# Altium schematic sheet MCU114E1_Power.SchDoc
size 431 x 279 mm; Date: Not shown in title block; ApprovedBy: Not shown in title block; CheckedBy: Not shown in title block; Author: Not shown in title block; CompanyName: Not shown in title block; Engineer: Not shown in title block; Organization: Not shown in title block; Address1: Not shown in title block; Address2: Not shown in title block; Address3: Not shown in title block; Address4: Not shown in title block; DocumentNumber: 5; Revision: Use project parameter SCH_Rev; SheetNumber: 5; SheetTotal: 11; PageSetup: Record=PageOptions¦CenterHorizontal=True¦CenterVertical=True¦PrintScale=1.00¦XCorrection=1.00¦YCorrection=1.00¦PrintKind=0¦BorderSize=5000000¦LeftOffset=0¦BottomOffset=0¦Orientation=2¦PaperLength=1000¦PaperWidth=1000¦Scale=100¦PaperSource=15¦PrintQuality=600¦MediaType=1¦DitherType=10¦PaperKind=Letter¦PrintScaleMode=1
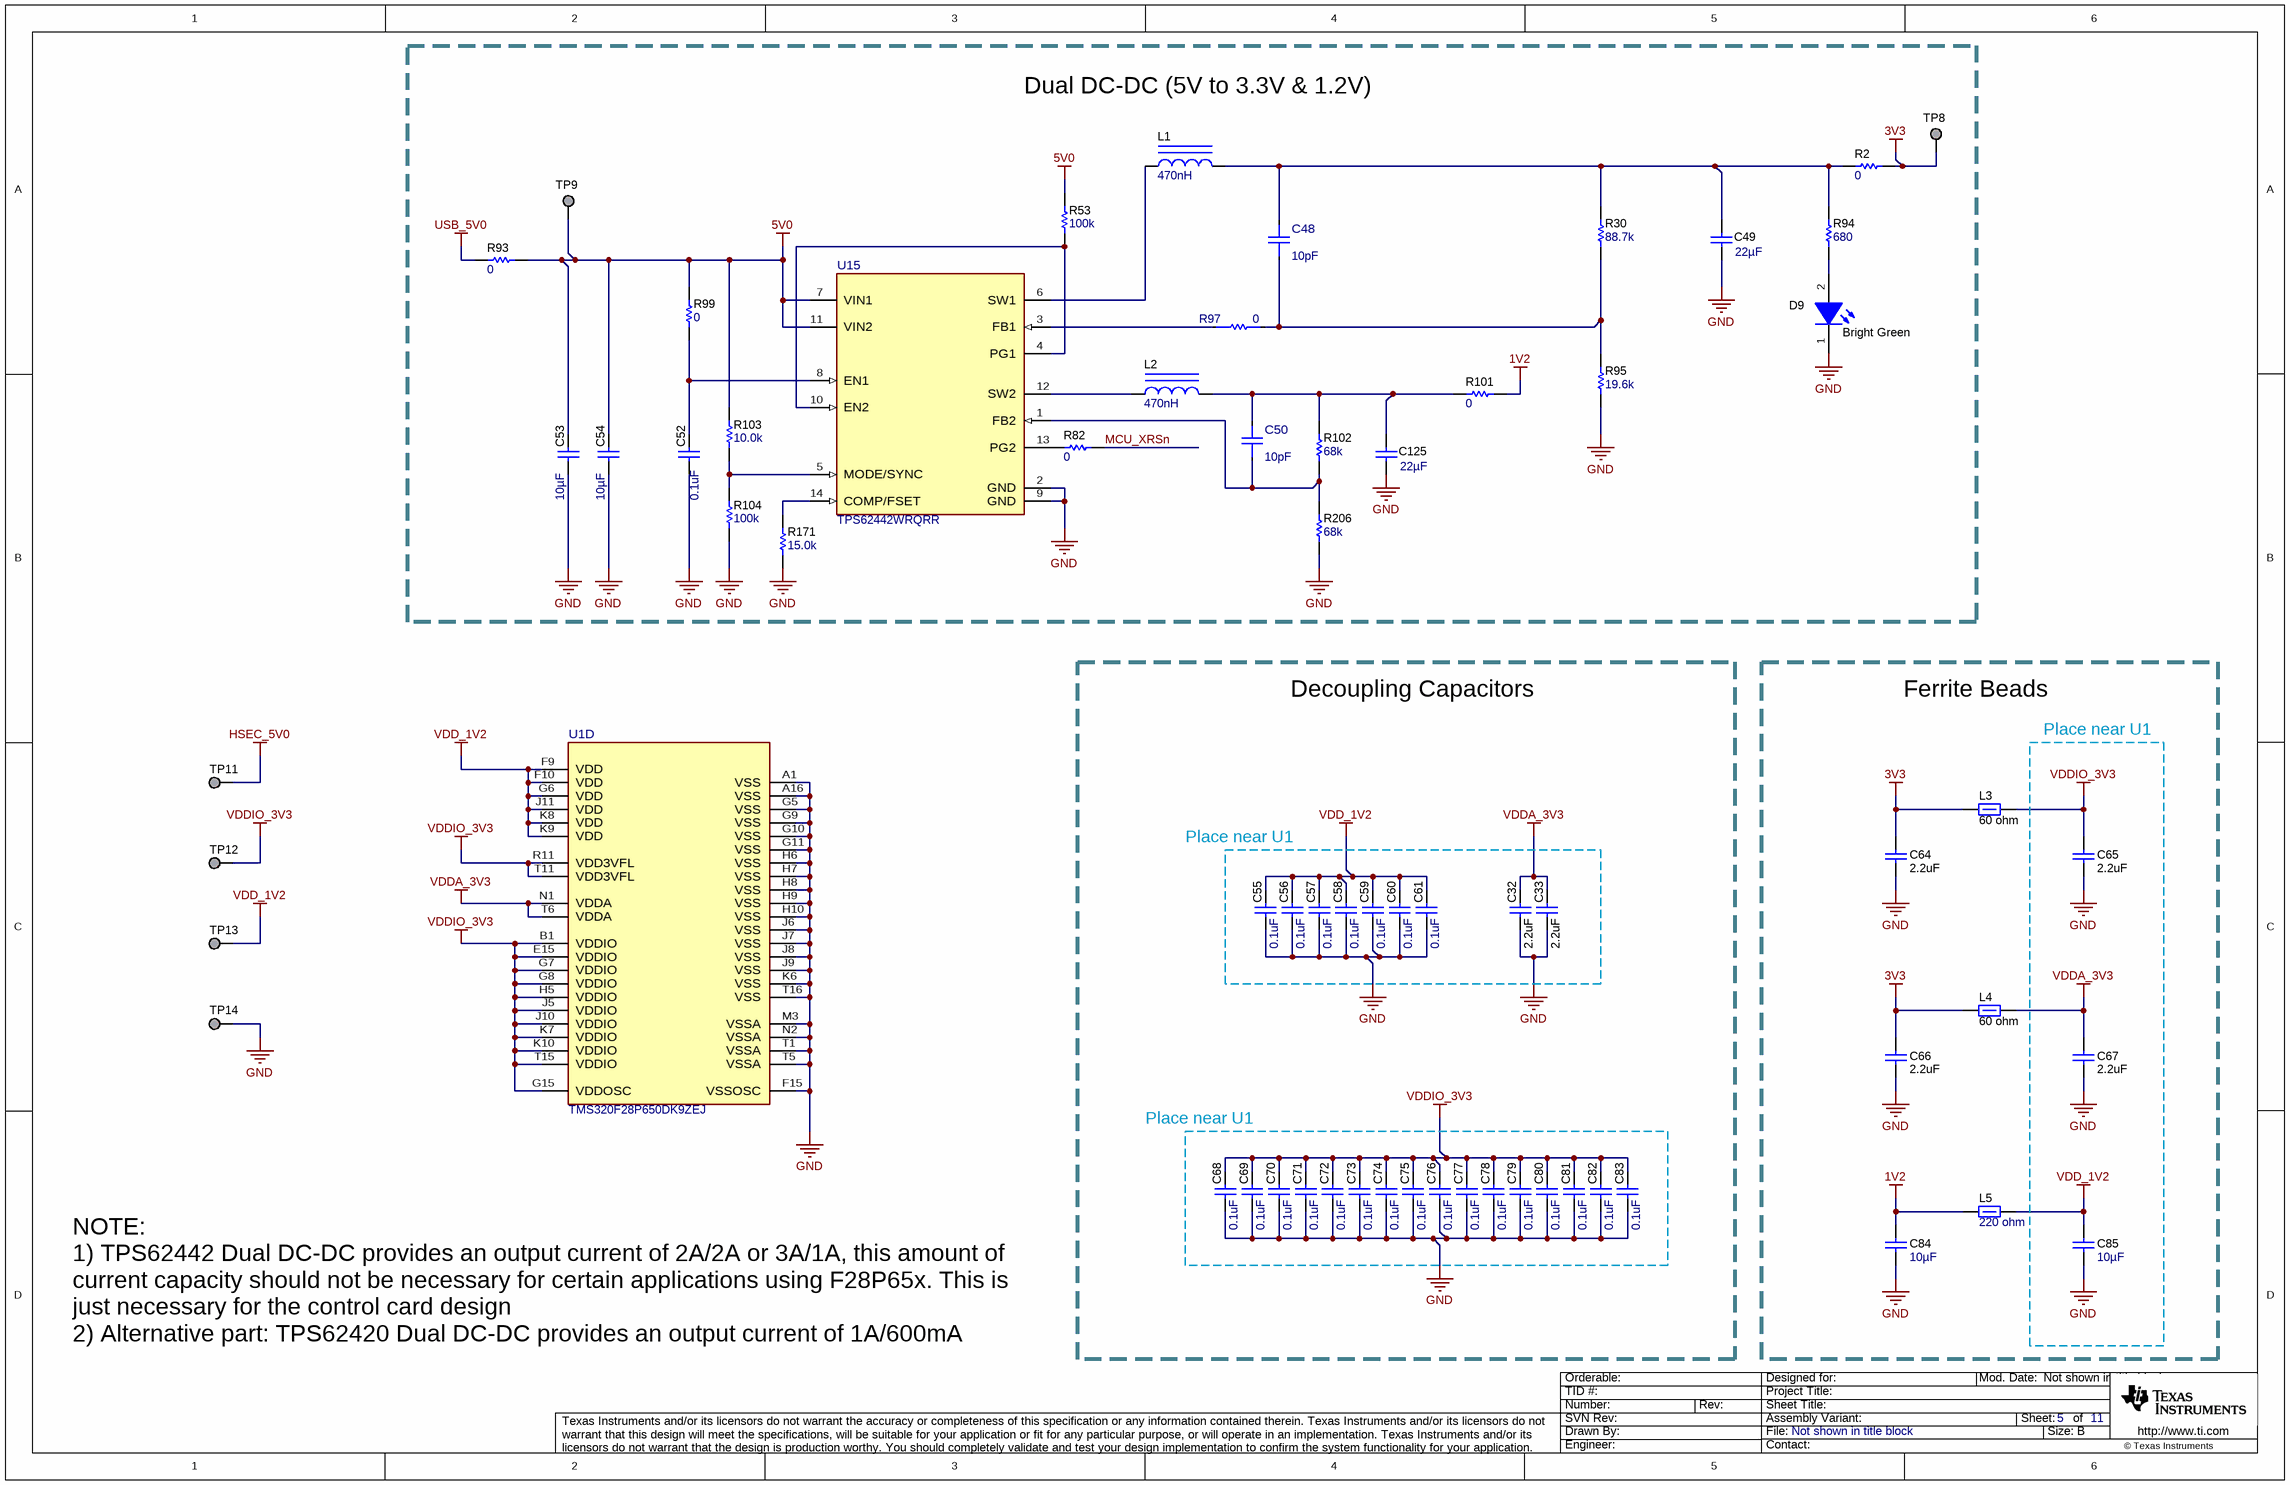
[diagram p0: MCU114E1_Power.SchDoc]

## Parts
C32  ValueDisplayed: 2.2uF  [0603]  (hidden comment: 885012106018)
C33  ValueDisplayed: 2.2uF  [0603]  (hidden comment: 885012106018)
C48  ValueDisplayed: 10pF  [FP-06033A100JAT2A_0603-MFG]  (hidden comment: 06033A100JAT2A)
C49  ValueDisplayed: 22µF  [0805_150]  (hidden comment: 885012107011)
C50  ValueDisplayed: 10pF  [FP-06033A100JAT2A_0603-MFG]  (hidden comment: 06033A100JAT2A)
C52  ValueDisplayed: 0.1uF  [0402]  (hidden comment: 885012205037)
C53  ValueDisplayed: 10µF  [0603]  (hidden comment: GRM188R61C106KAALD)
C54  ValueDisplayed: 10µF  [0603]  (hidden comment: GRM188R61C106KAALD)
C55  ValueDisplayed: 0.1uF  [0402]  (hidden comment: 885012205037)
C56  ValueDisplayed: 0.1uF  [0402]  (hidden comment: 885012205037)
C57  ValueDisplayed: 0.1uF  [0402]  (hidden comment: 885012205037)
C58  ValueDisplayed: 0.1uF  [0402]  (hidden comment: 885012205037)
C59  ValueDisplayed: 0.1uF  [0402]  (hidden comment: 885012205037)
C60  ValueDisplayed: 0.1uF  [0402]  (hidden comment: 885012205037)
C61  ValueDisplayed: 0.1uF  [0402]  (hidden comment: 885012205037)
C64  ValueDisplayed: 2.2uF  [0603]  (hidden comment: 885012106018)
C65  ValueDisplayed: 2.2uF  [0603]  (hidden comment: 885012106018)
C66  ValueDisplayed: 2.2uF  [0603]  (hidden comment: 885012106018)
C67  ValueDisplayed: 2.2uF  [0603]  (hidden comment: 885012106018)
C68  ValueDisplayed: 0.1uF  [0402]  (hidden comment: 885012205037)
C69  ValueDisplayed: 0.1uF  [0402]  (hidden comment: 885012205037)
C70  ValueDisplayed: 0.1uF  [0402]  (hidden comment: 885012205037)
C71  ValueDisplayed: 0.1uF  [0402]  (hidden comment: 885012205037)
C72  ValueDisplayed: 0.1uF  [0402]  (hidden comment: 885012205037)
C73  ValueDisplayed: 0.1uF  [0402]  (hidden comment: 885012205037)
C74  ValueDisplayed: 0.1uF  [0402]  (hidden comment: 885012205037)
C75  ValueDisplayed: 0.1uF  [0402]  (hidden comment: 885012205037)
C76  ValueDisplayed: 0.1uF  [0402]  (hidden comment: 885012205037)
C77  ValueDisplayed: 0.1uF  [0402]  (hidden comment: 885012205037)
C78  ValueDisplayed: 0.1uF  [0402]  (hidden comment: 885012205037)
C79  ValueDisplayed: 0.1uF  [0402]  (hidden comment: 885012205037)
C80  ValueDisplayed: 0.1uF  [0402]  (hidden comment: 885012205037)
C81  ValueDisplayed: 0.1uF  [0402]  (hidden comment: 885012205037)
C82  ValueDisplayed: 0.1uF  [0402]  (hidden comment: 885012205037)
C83  ValueDisplayed: 0.1uF  [0402]  (hidden comment: 885012205037)
C84  ValueDisplayed: 10µF  [0603]  (hidden comment: GRM188R61C106KAALD)
C85  ValueDisplayed: 10µF  [0603]  (hidden comment: GRM188R61C106KAALD)
C125  ValueDisplayed: 22µF  [0805_150]  (hidden comment: 885012107011)
D9  value Bright Green  [WL-SMCW_Green_0805]  (hidden comment: 150080VS75000)
L1  ValueDisplayed: 470nH  [XFL4015]  (hidden comment: XFL4015-471MEC)
L2  ValueDisplayed: 470nH  [XFL4015]  (hidden comment: XFL4015-471MEC)
L3  60 ohm  [0805_HV]
L4  60 ohm  [0805_HV]
L5  value 220 ohm  [0805_HV]  (hidden comment: BLM21PG221SN1D)
R2  ValueDisplayed: 0  [0402]  (hidden comment: CRCW04020000Z0EDHP)
R30  ValueDisplayed: 88.7k  [0402]  (hidden comment: CRCW040288K7FKED)
R53  ValueDisplayed: 100k  [0603]  (hidden comment: CRCW0603100KJNEA)
R82  ValueDisplayed: 0  [0402]  (hidden comment: CRCW04020000Z0EDHP)
R93  ValueDisplayed: 0  [0402]  (hidden comment: CRCW04020000Z0EDHP)
R94  ValueDisplayed: 680  [0402]  (hidden comment: CRCW0402680RJNED)
R95  ValueDisplayed: 19.6k  [0402]  (hidden comment: CRCW040219K6FKED)
R97  0  [FP-CRCW04020000Z0EDC_0402-MFG]
R99  ValueDisplayed: 0  [0402]  (hidden comment: CRCW04020000Z0EDHP)
R101  ValueDisplayed: 0  [0402]  (hidden comment: CRCW04020000Z0EDHP)
R102  ValueDisplayed: 68k  [0402]  (hidden comment: CRCW040268K0JNED)
R103  ValueDisplayed: 10.0k  [0402]  (hidden comment: AC0402FR-0710KL)
R104  ValueDisplayed: 100k  [0603]  (hidden comment: CRCW0603100KJNEA)
R171  ValueDisplayed: 15.0k  [0402]  (hidden comment: CRCW040215K0FKED)
R206  ValueDisplayed: 68k  [0402]  (hidden comment: CRCW040268K0JNED)
TP8  TESTPOINT  [TP_50MIL-25MILHOLE]  (value not drawn)  (no BOM)
TP9  TESTPOINT  [TP_50MIL-25MILHOLE]  (value not drawn)  (no BOM)
TP11  TESTPOINT  [TP_50MIL-25MILHOLE]  (value not drawn)  (no BOM)
TP12  TESTPOINT  [TP_50MIL-25MILHOLE]  (value not drawn)  (no BOM)
TP13  TESTPOINT  [TP_50MIL-25MILHOLE]  (value not drawn)  (no BOM)
TP14  TESTPOINT  [TP_50MIL-25MILHOLE]  (value not drawn)  (no BOM)
U1  TMS320F28P650DK9ZEJ  [ZEJ0256A-MFG]  (part D of 4)
U15  TPS62442WRQRR  [RQR0014A-MFG]

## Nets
1V2: C84.1 L5.1 R101.2
3V3: C64.1 C66.1 L3.1 L4.1 R2.2 TP8.1
5V0: C53.1 C54.1 R53.2 R93.1 R99.2 R103.2 TP9.1 U15.7(VIN1) U15.11(VIN2)
GND: C32.2 C33.2 C49.2 C52.2 C53.2 C54.2 C55.2 C56.2 C57.2 C58.2 C59.2 C60.2 C61.2 C64.2 C65.2 C66.2 C67.2 C68.2 C69.2 C70.2 C71.2 C72.2 C73.2 C74.2 C75.2 C76.2 C77.2 C78.2 C79.2 C80.2 C81.2 C82.2 C83.2 C84.2 C85.2 C125.2 D9.1(K) R95.1 R104.1 R171.1 R206.1 TP14.1 U1.A1(VSS) U1.A16(VSS) U1.F15(VSSOSC) U1.G5(VSS) U1.G9(VSS) U1.G10(VSS) U1.G11(VSS) U1.H6(VSS) U1.H7(VSS) U1.H8(VSS) U1.H9(VSS) U1.H10(VSS) U1.J6(VSS) U1.J7(VSS) U1.J8(VSS) U1.J9(VSS) U1.K6(VSS) U1.M3(VSSA) U1.N2(VSSA) U1.T1(VSSA) U1.T5(VSSA) U1.T16(VSS) U15.2(GND) U15.9(GND)
HSEC_5V0: TP11.1
USB_5V0: R93.2
VDD_1V2: C55.1 C56.1 C57.1 C58.1 C59.1 C60.1 C61.1 C85.1 L5.2 TP13.1 U1.F9(VDD) U1.F10(VDD) U1.G6(VDD) U1.J11(VDD) U1.K8(VDD) U1.K9(VDD)
VDDA_3V3: C32.1 C33.1 C67.1 L4.2 U1.N1(VDDA) U1.T6(VDDA)
VDDIO_3V3: C65.1 C68.1 C69.1 C70.1 C71.1 C72.1 C73.1 C74.1 C75.1 C76.1 C77.1 C78.1 C79.1 C80.1 C81.1 C82.1 C83.1 L3.2 TP12.1 U1.B1(VDDIO) U1.E15(VDDIO) U1.G7(VDDIO) U1.G8(VDDIO) U1.G15(VDDOSC) U1.H5(VDDIO) U1.J5(VDDIO) U1.J10(VDDIO) U1.K7(VDDIO) U1.K10(VDDIO) U1.R11(VDD3VFL) U1.T11(VDD3VFL) U1.T15(VDDIO)
MCU_XRSn: R82.1
NetC48_1: C48.1 R30.1 R95.2 R97.2
NetC48_2: C48.2 C49.1 L1.2 R2.1 R30.2 R94.2
NetC50_1: C50.1 R102.1 R206.2 U15.1(FB2)
NetC50_2: C50.2 C125.1 L2.2 R101.1 R102.2
NetC52_1: C52.1 R99.1 U15.8(EN1)
NetD9_2: D9.2(A) R94.1
NetL1_1: L1.1 U15.6(SW1)
NetL2_1: L2.1 U15.12(SW2)
NetR53_1: R53.1 U15.4(PG1) U15.10(EN2)
NetR82_2: R82.2 U15.13(PG2)
NetR97_1: R97.1 U15.3(FB1)
NetR103_1: R103.1 R104.2 U15.5(MODE/SYNC)
NetR171_2: R171.2 U15.14(COMP/FSET)

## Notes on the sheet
- Dual DC-DC (5V to 3.3V & 1.2V)
- Decoupling Capacitors
- Ferrite Beads
- Place near U1
- NOTE:
  1) TPS62442 Dual DC-DC provides an output current of 2A/2A or 3A/1A, this amount of current capacity should not be necessary for certain applications using F28P65x. This is just necessary for the control card design
  2) Alternative part: TPS62420 Dual DC-DC provides an output current of 1A/600mA

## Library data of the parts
C32 C33 C64-C67 = CMP-0006825-5: CAP, CERM, 2.2 uF, 16 V, +/- 20%, X5R, 0603; Manufacturer: Wurth Elektronik; TaMin_C: -55°C; Polarized: N; SizeAreaWB_mm2: 4.68; Value1: Unknown; U/M: EA; Value: 2.2uF; TaMax_C: 85°C; SizeZ_mm: 1; SizeX_mm: 1.6; SizeY_mm: 0.8; Value2: 16V; SizeArea_mm2: 1.28; Cap_F: 2.2µF; AEC Category: Q200
C48 C50 = CMP-0090724-1: 10pF ±5% 25V Ceramic Capacitor C0G, NP0 0603 (1608 Metric); Manufacturer: AVX; TempCo: 30ppm/°C; AEC Qualified: No; SizeZ_mm: 0.9mm
C49 C125 = CMP-0078153-1: CAP, CERM, 22 µF, 10 V,+/- 20%, X5R, 0805; Manufacturer: Wurth Elektronik; TaMin_C: -55°C; Polarized: N; SizeAreaWB_mm2: 6.75; U/M: EA; Value: 22uF; TaMax_C: 85°C; SizeZ_mm: 1.5; SizeX_mm: 2; SizeY_mm: 1.25; Cap_Case: 0805; Value2: 10V; SizeArea_mm2: 2.5; AEC Category: Q200
C52 C55-C61 C68-C83 = CMP-0006228-2: CAP, CERM, 0.1 uF, 16 V, +/- 10%, X7R, 0402; Manufacturer: Wurth Elektronik; TaMin_C: -55°C; Polarized: N; SizeAreaWB_mm2: 3; Value1: Unknown; U/M: EA; Value: 0.1uF; TaMax_C: 125°C; SizeZ_mm: 0.6; SizeX_mm: 1; SizeY_mm: 0.5; Value2: 16V; Cap_F: 100nF; AEC Category: Q200
C53 C54 C84 C85 = CMP-0086225-1: CAP, CERM, 10 µF, 16 V,+/- 10%, X5R, 0603; Manufacturer: MuRata; SizeZ_mm: 1; SizeX_mm: 1.6; SizeArea_mm2: 1.28; VDC_V: 16V; U/M: EA; AEC Category: Q200; SizeY_mm: 0.8; Polarized: N; TaMax_C: 85°C; Value: 10uF; SizeAreaWB_mm2: 4.68; TaMin_C: -55°C
D9 = CMP-0002960-2: LED, Bright Green, SMD; Manufacturer: Wurth Elektronik; Type: AlInGaP; Vf_V: 2V; Io_A: 20mA; Vr_V: 5V; Tjmax_C: 85°C; Power_TotalModule: 72mW; Value1: 0.072W; Angle: 140; U/M: EA
L1 L2 = CMP-0061147-1: Inductor, Shielded, Composite, 470 nH, 3.5 A, 0.0076 ohm, SMD; Manufacturer: Coilcraft; Isat: 3.5A @ 10% inductance drop; Irms: 9.1A @ 20C rise; Green_Lifecycle: Not Set; SizeAreaWB_mm2: 28.09; DCR_ohm: 7.6m; Green_REACh: Incomplete; Value: 470nH; Imax_A: 3.5A; SizeZ_mm: 1.6; SizeX_mm: 4.3; SizeArea_mm2: 18.49; AEC Category: Q200
L3 L4 = CMP-0003093-1: Ferrite Bead, 60 ohm @ 100 MHz, 3 A, 0805; Manufacturer: Wurth Elektronik; PartNumber: 742792063; Ztyp@1GHz_Ohm: 95.384; ZTyp@100MHz_Ohm: 60; SizeAreaWB_mm2: 6.75; DCR_ohm: 0.025; Value1: 0.025 ohm; Imax_A: 3A; SizeZ_mm: 1.45; SizeX_mm: 2; SizeY_mm: 1.25; SizeArea_mm2: 2.5
L5 = CMP-0003363-1: Ferrite Bead, 220 ohm @ 100 MHz, 2 A, 0805; Manufacturer: MuRata; Imax_A: 2A; DCR_ohm: 45m; Value1: 0.045 ohm; ZTyp@100MHz_Ohm: 220; SizeArea_mm2: 2.5; SizeAreaWB_mm2: 6.75; SizeX_mm: 2; SizeY_mm: 1.25; SizeZ_mm: 1.45
R2 R82 R93 R99 R101 = CMP-0081856-1: RES, 0, 0%, 0.2 W, AEC-Q200 Grade 0, 0402; Manufacturer: Vishay-Dale; SizeAreaWB_mm2: 3; SizeArea_mm2: 0.5; AEC Qualified: Y; AEC Category: Q200; Value: 0; SizeZ_mm: 0.6; Power_W: 200mW; VDC_V: 50V; Value2: 0.2W; SizeX_mm: 1
R30 = CMP-0026586-2: RES, 88.7 k, 1%, 0.063 W, AEC-Q200 Grade 0, 0402; Manufacturer: Vishay-Dale; Power_W: 63mW; TempCo: 100 ppm/C; Value_Code: 88k7; Value: 88.7k; EIA_Code: E96; SizeX_mm: 1; SizeY_mm: 0.5; SizeZ_mm: 0.6; Value2: 0.063W; AEC Qualified: Y; VDC_V: 50V; AEC Category: Q200; AEC Grade: 0
R53 R104 = CMP-0025698-4: RES, 100 k, 5%, 0.1 W, AEC-Q200 Grade 0, 0603; Manufacturer: Vishay-Dale; Power_W: 100mW; TempCo: 200 ppm/C; Value: 100k; EIA_Code: E24; SizeX_mm: 1.6; SizeY_mm: 0.8; SizeZ_mm: 1; Value2: 0.1W; SizeArea_mm2: 1.28; AEC Qualified: Y; VDC_V: 75V; AEC Category: Q200; AEC Grade: 0
R94 = CMP-0026962-3: RES, 680, 5%, 0.063 W, AEC-Q200 Grade 0, 0402; Manufacturer: Vishay-Dale; Power_W: 63mW; TempCo: 200 ppm/C; Value_Code: 680R; Value: 680; EIA_Code: E24; SizeX_mm: 1; SizeY_mm: 0.5; SizeZ_mm: 0.6; Value2: 0.063W; AEC Qualified: Y; VDC_V: 50V; AEC Category: Q200; AEC Grade: 0
R95 = CMP-0026068-3: RES, 19.6 k, 1%, 0.063 W, AEC-Q200 Grade 0, 0402; Manufacturer: Vishay-Dale; Power_W: 63mW; TempCo: 100 ppm/C; Value_Code: 19k6; Value: 19.6k; EIA_Code: E96; SizeX_mm: 1; SizeY_mm: 0.5; SizeZ_mm: 0.6; Value2: 0.063W; AEC Qualified: Y; VDC_V: 50V; AEC Category: Q200; AEC Grade: 0
R97 = CMP-0093210-1: Jumper 0.063W, 1/16W Chip Resistor 0402 (1005 Metric) - Thick Film; Manufacturer: Vishay; Part Number: CRCW04020000Z0EDC; AEC Qualified: No; VDC_V: 50V; Power_W: 63mW; SizeZ_mm: 0.35mm
R102 R206 = CMP-0026963-3: RES, 68 k, 5%, 0.063 W, AEC-Q200 Grade 0, 0402; Manufacturer: Vishay-Dale; Power_W: 63mW; TempCo: 200 ppm/C; Value_Code: 68k0; Value: 68k; EIA_Code: E24; SizeX_mm: 1; SizeY_mm: 0.5; SizeZ_mm: 0.6; Value2: 0.063W; AEC Qualified: Y; VDC_V: 50V; AEC Category: Q200; AEC Grade: 0
R103 = CMP-0077731-1: RES, 10.0 k, 1%, 0.063 W, AEC-Q200 Grade 0, 0402; Manufacturer: Yageo America; Power_W: 63mW; TempCo: 100 ppm/C; Value_Code: 10k0; U/M: EA; Value: 10.0k; EIA_Code: E96; Res_ohm: 10k; SizeX_mm: 1.0; SizeY_mm: 0.5; SizeZ_mm: 0.6; Value2: 0.063W; AEC Qualified: Y; VDC_V: 50V; AEC Grade: 0; AEC Category: Q200
R171 = CMP-0026027-3: RES, 15.0 k, 1%, 0.063 W, AEC-Q200 Grade 0, 0402; Manufacturer: Vishay-Dale; Power_W: 63mW; TempCo: 100 ppm/C; Value_Code: 15k0; Value: 15.0k; EIA_Code: E96; Res_ohm: 15k; SizeX_mm: 1; SizeY_mm: 0.5; SizeZ_mm: 0.6; Value2: 0.063W; AEC Qualified: Y; VDC_V: 50V; AEC Category: Q200; AEC Grade: 0
TP8 TP9 TP11-TP14 = CMP-0078143-3: TEST POINT.  No entry in BOM.
U1 = CMP-0096042-2: Real-Time Microcontroller NFBGA256; Manufacturer: Texas Instruments; AEC Category: Q200; Core Architecture: C28x; Data Bus Width: 32bits; Number Of Ethernet Channels: 1; Number Of Cores: 2; CompType: IC; Number Of I/Os: 159; Interface: I2C,SPI,UART,CAN,USB,LIN,SCI,Ethernet,Other; Number Of Pwm Channels: 36; AEC Qualified: No; Number Of Timers/Counters: 6; Standoff Height: 0.35mm; Number Of Spi Channels: 4; SizeZ_mm: 1.4mm; Number Of Adc Channels: 40; Ram Size: 248KBytes; Frequency_Fixed: 200MHz; Memory Size: 1.28MBytes; Number Of A/D Converters: 3; Memory Type: FLASH
U15 = CMP-0094192-1: 2.7-V to 6-V Adjustable-Frequency Dual Step-Down Converter in QFN package; Manufacturer: Texas Instruments; Number Of Outputs: 2; Max Duty Cycle: 100%; TaMin_C: -40°C; Standoff Height: 0mm; AEC Grade: NA; AEC Qualified: No; Output Type: AdjustableProgrammable; Max Supply Voltage: 6V; Min Supply Voltage: 2.7V; TaMax_C: +125°C; SizeZ_mm: 1mm; Switching Topology: Buck; TJmax_C: +150°C; Output Voltage: 0.6-5.5V; Nominal Supply Current: 22-33uA; Switching Frequency: 1.8-4MHz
